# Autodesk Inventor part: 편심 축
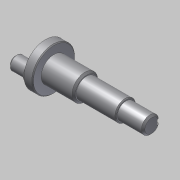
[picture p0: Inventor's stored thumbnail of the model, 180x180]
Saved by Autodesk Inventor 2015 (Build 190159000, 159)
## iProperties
Created: 2015-10
Part Number: 편심 축
Document SubType Name: Modeling
Designer: mdu
Density: 7.86 g/cm^3
Material: 강철, 연강
Mass: 78.4913 g
Surface Area: 37.9919 cm^2
Volume: 9.98617 cm^3
Appearance: Default
Author: mdu
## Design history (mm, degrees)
sketch "스케치1"
  geometry: L1 (1.75, -12.001)-(1.75, 11.999) reference; L2 (-16.95, -14)-(-16.95, 14) reference; L3 (-36.25, -18.06)-(-36.25, 18.06) reference; L4 (-41.25, 0)-(20.75, 0); L5 (-41.25, 0)-(-41.25, 12.5); L6 (-41.25, 12.5)-(-36.25, 12.5); L7 (-36.25, 12.5)-(-36.25, 7.5); L8 (-36.25, 7.5)-(-17.25, 7.5); L9 (-17.25, 6)-(5.75, 6); L10 (20.75, 5)-(20.75, 0); L11 (5.75, 6)-(5.75, 5); L12 (5.75, 5)-(20.75, 5); L13 (-17.25, -13.7)-(-17.25, 13.7) reference; L14 (-17.25, 7.5)-(-17.25, 6); 2 further points
  constraints: 20 end point, 7 perpendicular, 5 point on line, 1 collinear, 1 midpoint, 1 parallel
  dimensions: "d0" = 12 diameter of L9 L4; "d1" = 15 diameter of L8 L4; "d2" = 25 diameter of L6 L4; "d3" = 5 distance of L5.end L6.end; "d4" = 62 distance of L4.start L4.end; "d5" = 10 diameter of L12 L4; "d6" = 15 distance of L11.end L10.start
revolve "회전1" sketch "스케치1" stored, may be unused: angle "d7" = 90 deg
sketch "스케치2"
  geometry: C1 r 4 at (0, -7.5); C2 r 5 at (0, -7.5); C3 r 12.5 at (0, 0) reference; 1 further point
  constraints: 2 centre point, 1 coincident, 1 tangent, 1 vertical alignment
  dimensions: "d8" = 8 diameter of C1; "d9" = 7.5 distance of point (0, 0) C1.centre
extrude "돌출1" join sketch "스케치2" distance "d10" = 10; taper "d11" = 0 deg
extrude "돌출2" join sketch "스케치2" distance "d12" = 0.5; taper "d13" = 0 deg
node "작업 평면1"
sketch "스케치3"
  geometry: L1 (-7.5, 5)-(-7.5, -5) reference; L2 (-7.5, 1.5)-(3, 1.5); L3 (3, -1.5)-(-7.5, -1.5); A1 r 1.5 centre (3, 0) between (3, -1.5) and (3, 1.5); 2 further points
  constraints: 4 end point, 2 perpendicular, 2 point on circle, 2 point on line, 2 tangent, 1 centre point, 1 horizontal alignment, 1 midpoint
  dimensions: "d14" = 3 distance between parallel lines of L3 L2; "d15" = 12 dimension on A1 L1
extrude "돌출3" cut sketch "스케치3" distance "d16" = 1.8; taper "d17" = 0 deg
chamfer "모따기1" distance "d18" = 1; stored, may be unused: second distance "d19" = 2, angle "d20" = 45 deg
chamfer "모따기2" distance "d21" = 0.5; stored, may be unused: second distance "d22" = 2, angle "d23" = 45 deg
node "솔리드1"
node "참조1"
node "참조2"
node "참조3"
node "참조4"
